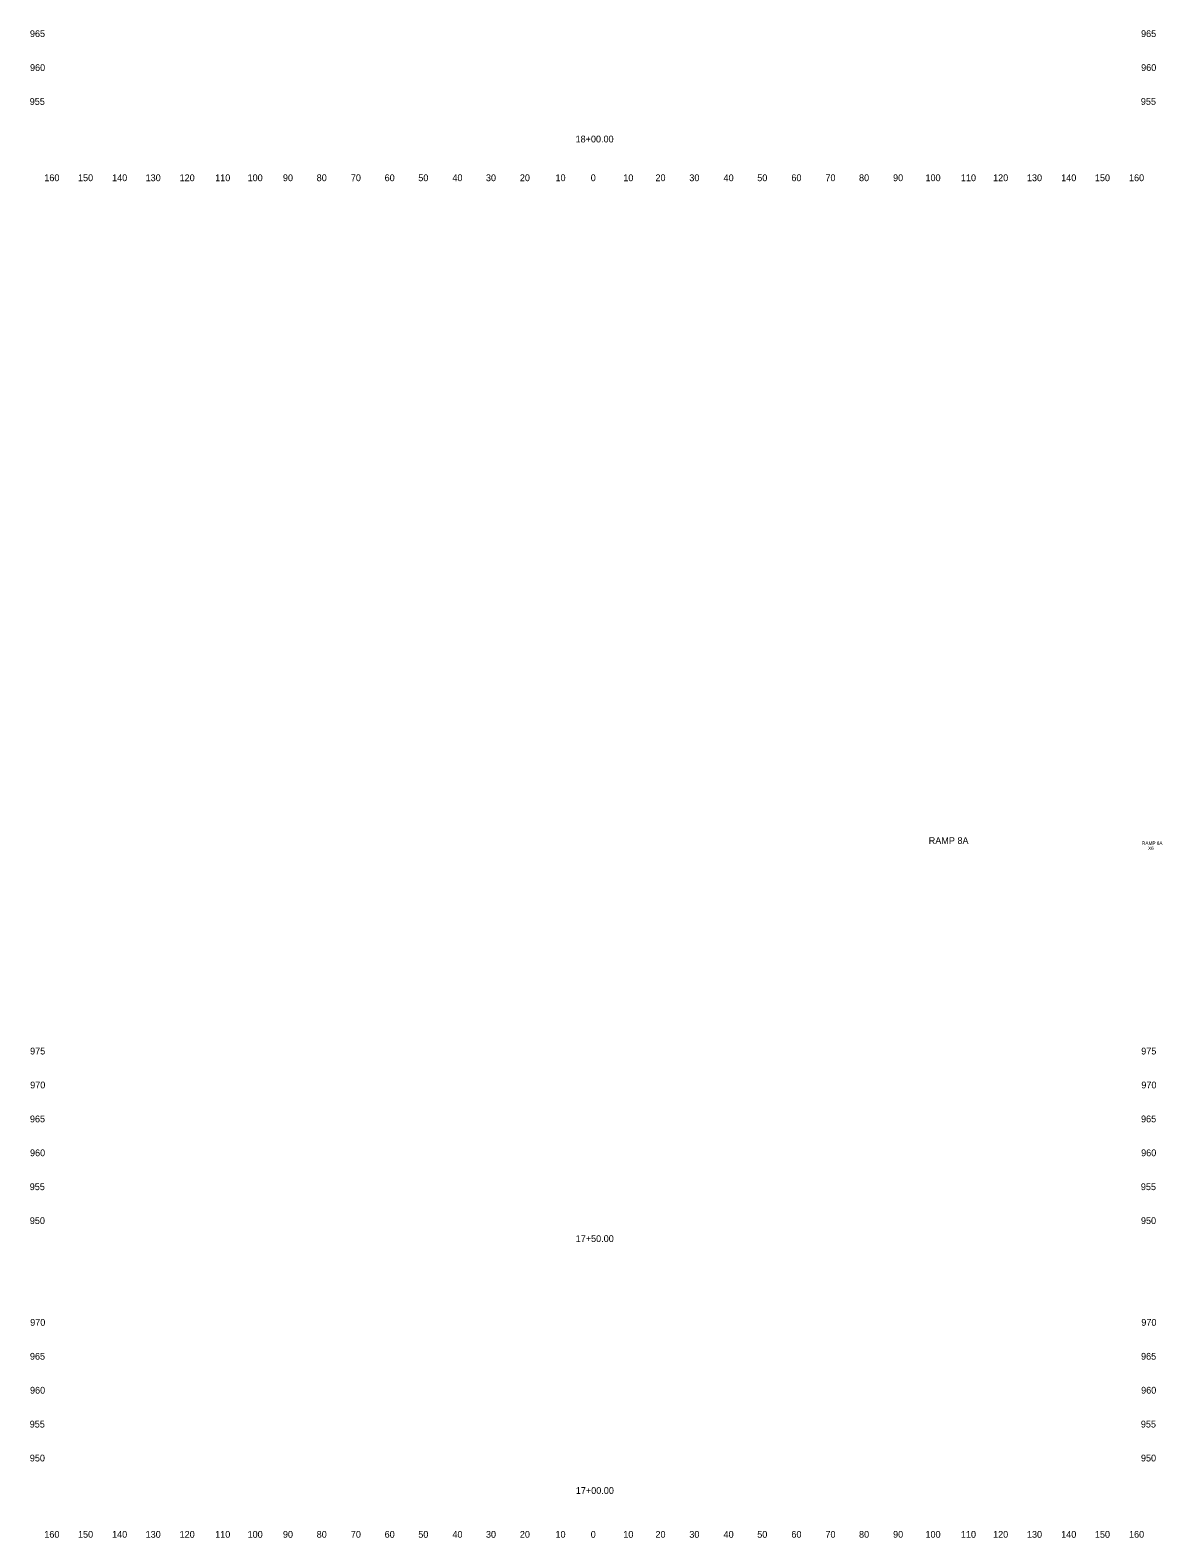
# Model space of a CAD drawing. Extents: x 4994 to 5328, y 4997 to 8804.
# Drawn here: x 4993.9 to 5327.8, y 6997.5 to 7442 of the extents above; entities that cross this region are included whole.
import ezdxf

# ---------------------------------------------------------------- set-up
doc = ezdxf.new("R2010")
doc.units = 0
for name, color, linetype in [('RD_SHT_ID', 7, 'Continuous'), ('RD_XS_TX_Offset', 7, 'Continuous'), ('RD_XS_TX_Station', 7, 'Continuous')]:
    doc.layers.add(name, color=color, linetype=linetype)

msp = doc.modelspace()

# ---------------------------------------------------------------- texts
at = {"layer": 'RD_SHT_ID'}
for s, height, p in [('RAMP 8A', 2, (5259.02, 7202.06)), ('RAMP 8A', 1, (5321.93, 7201.8)), ('X6', 1, (5323.71, 7200.3))]:
    msp.add_text(s, height=height, dxfattribs=at).set_placement(p)
at = {"layer": 'RD_XS_TX_Offset'}
for s, p in [('965', (4993.86, 7440)), ('965', (5321.66, 7440)), ('960', (4993.89, 7430)), ('960', (5321.69, 7430)), ('955', (4993.8, 7420)), ('955', (5321.6, 7420)), ('160', (4998.1, 7397.5)), ('150', (5008.04, 7397.5)), ('140', (5018.1, 7397.5)), ('130', (5027.99, 7397.5)), ('120', (5038.01, 7397.5)), ('110', (5048.51, 7397.5)), ('100', (5058.07, 7397.5)), ('90', (5068.5, 7397.5)), ('80', (5078.46, 7397.5)), ('70', (5088.54, 7397.5)), ('60', (5098.5, 7397.5)), ('50', (5108.43, 7397.5)), ('40', (5118.5, 7397.5)), ('30', (5128.39, 7397.5)), ('20', (5138.4, 7397.5)), ('10', (5148.91, 7397.5)), ('0', (5159.3, 7397.5)), ('0', (5159.3, 7397.5)), ('10', (5168.91, 7397.5)), ('20', (5178.4, 7397.5)), ('30', (5188.39, 7397.5)), ('40', (5198.5, 7397.5)), ('50', (5208.43, 7397.5)), ('60', (5218.5, 7397.5)), ('70', (5228.54, 7397.5)), ('80', (5238.46, 7397.5)), ('90', (5248.5, 7397.5)), ('100', (5258.07, 7397.5)), ('110', (5268.51, 7397.5)), ('120', (5278.01, 7397.5)), ('130', (5287.99, 7397.5)), ('140', (5298.1, 7397.5)), ('150', (5308.04, 7397.5)), ('160', (5318.1, 7397.5)), ('975', (4993.91, 7140)), ('975', (5321.71, 7140)), ('970', (4993.94, 7130)), ('970', (5321.74, 7130)), ('965', (4993.86, 7120)), ('965', (5321.66, 7120)), ('960', (4993.89, 7110)), ('960', (5321.69, 7110)), ('955', (4993.8, 7100)), ('955', (5321.6, 7100)), ('950', (4993.83, 7090)), ('950', (5321.63, 7090)), ('970', (4993.94, 7060)), ('970', (5321.74, 7060)), ('965', (4993.86, 7050)), ('965', (5321.66, 7050)), ('960', (4993.89, 7040)), ('960', (5321.69, 7040)), ('955', (4993.8, 7030)), ('955', (5321.6, 7030)), ('950', (4993.83, 7020)), ('950', (5321.63, 7020)), ('160', (4998.1, 6997.5)), ('150', (5008.04, 6997.5)), ('140', (5018.1, 6997.5)), ('130', (5027.99, 6997.5)), ('120', (5038.01, 6997.5)), ('110', (5048.51, 6997.5)), ('100', (5058.07, 6997.5)), ('90', (5068.5, 6997.5)), ('80', (5078.46, 6997.5)), ('70', (5088.54, 6997.5)), ('60', (5098.5, 6997.5)), ('50', (5108.43, 6997.5)), ('40', (5118.5, 6997.5)), ('30', (5128.39, 6997.5)), ('20', (5138.4, 6997.5)), ('10', (5148.91, 6997.5)), ('0', (5159.3, 6997.5)), ('0', (5159.3, 6997.5)), ('10', (5168.91, 6997.5)), ('20', (5178.4, 6997.5)), ('30', (5188.39, 6997.5)), ('40', (5198.5, 6997.5)), ('50', (5208.43, 6997.5)), ('60', (5218.5, 6997.5)), ('70', (5228.54, 6997.5)), ('80', (5238.46, 6997.5)), ('90', (5248.5, 6997.5)), ('100', (5258.07, 6997.5)), ('110', (5268.51, 6997.5)), ('120', (5278.01, 6997.5)), ('130', (5287.99, 6997.5)), ('140', (5298.1, 6997.5)), ('150', (5308.04, 6997.5)), ('160', (5318.1, 6997.5))]:
    msp.add_text(s, height=2, dxfattribs=at).set_placement(p)
at = {"layer": 'RD_XS_TX_Station'}
for s, p in [('18+00.00', (5154.83, 7408.92)), ('17+50.00', (5154.87, 7084.7)), ('17+00.00', (5154.91, 7010.43))]:
    msp.add_text(s, height=2, dxfattribs=at).set_placement(p)

doc.saveas('drawing.dxf')
